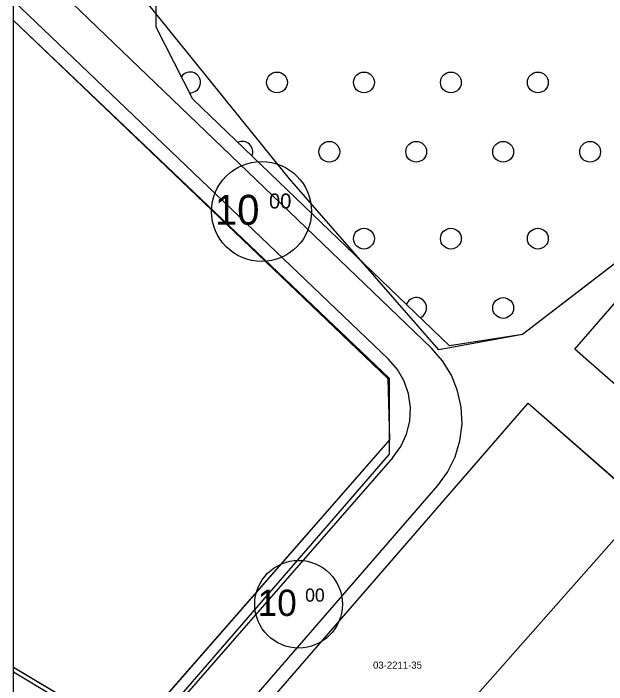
# Model space of a CAD drawing. Extents: x 413946 to 415528, y 4453939 to 4454944.
# Drawn here: x 413945.6 to 414028.6, y 4454334.2 to 4454428.2 of the extents above; entities that cross this region are included whole.
import ezdxf

# ---------------------------------------------------------------- set-up
doc = ezdxf.new("R2010")
doc.units = 0
for name, color, linetype in [('0_KADASTRO', 7, 'Continuous'), ('0_ÇERÇEVE', 7, 'Continuous'), ('Level 28', 7, 'Continuous'), ('Level 29', 7, 'Continuous'), ('Level 42', 7, 'Continuous'), ('Level 54', 7, 'Continuous'), ('Level 62', 7, 'Continuous'), ('SEMBOL', 7, 'Continuous')]:
    doc.layers.add(name, color=color, linetype=linetype)

msp = doc.modelspace()

# ---------------------------------------------------------------- linework, layer by layer
at = {"layer": '0_KADASTRO'}
for points in [[(414107.963, 4454432.627), (414089.276, 4454397.161), (414082.06, 4454401.15), (414059.63, 4454407.26), (414049.35, 4454408.22), (414042.038, 4454402.592), (414016.87, 4454383.22), (414005.15, 4454381.09), (413984.23, 4454405.06), (413963.56, 4454430.73)], [(413945.566, 4454335.9), (413945.566, 4454427.263)], [(413945.566, 4454427.263), (413998.2, 4454377.1), (413998.21, 4454366.46), (413962.78, 4454325.53), (413945.566, 4454335.9)]]:
    msp.add_lwpolyline(points, dxfattribs=at)
for points in [[(414024.21, 4454381.2), (414042.54, 4454402.37), (414065.08, 4454394.56), (414040.59, 4454366.81)], [(413971.79, 4454320.66), (414017.66, 4454373.64), (414033.97, 4454359.32), (413986.11, 4454305.11)], [(413986.11, 4454305.11), (414033.97, 4454359.32), (414065.92, 4454331.64), (414015.89, 4454273.36)]]:
    msp.add_lwpolyline(points, close=True, dxfattribs=at)
at = {"layer": '0_ÇERÇEVE'}
msp.add_lwpolyline([(413945.566, 4454943.957), (415494.137, 4454943.957), (415494.137, 4453939.478), (413945.566, 4453939.478)], close=True, dxfattribs=at)
at = {"layer": 'Level 28'}
for p, q in [((413945.566, 4454427.25), (413998.026, 4454377.098)), ((413970.715, 4454416.209), (413965.538, 4454426.303)), ((414006.623, 4454381.67), (413970.715, 4454416.209)), ((414049.35, 4454408.22), (414016.87, 4454383.22)), ((414016.87, 4454383.22), (414006.623, 4454381.67)), ((413998.026, 4454377.098), (413998.217, 4454368.455)), ((413971.79, 4454320.66), (414017.66, 4454373.64)), ((414017.66, 4454373.64), (414033.97, 4454359.32)), ((413998.217, 4454368.455), (413961.889, 4454326.835)), ((413961.889, 4454326.835), (413945.566, 4454336.587))]:
    msp.add_line(p, q, dxfattribs=at)
at = {"layer": 'Level 29'}
msp.add_line((413965.538, 4454426.303), (413965.538, 4454441.044), dxfattribs=at)
at = {"layer": 'Level 42'}
for centre in [(413982.483, 4454418.578), (413994.661, 4454418.578), (414006.839, 4454418.578), (414019.017, 4454418.578), (413989.801, 4454408.858), (414001.979, 4454408.858), (414014.157, 4454408.858), (414026.335, 4454408.858), (413994.661, 4454396.68), (414006.839, 4454396.68), (414019.017, 4454396.68), (414014.157, 4454386.96)]:
    msp.add_circle(centre, 1.458, dxfattribs=at)
for centre, start, end in [((413970.305, 4454418.578), 267.72643, 146.57823), ((413977.623, 4454408.858), 336.55024, 115.67635), ((414001.979, 4454386.96), 292.10672, 160.11986)]:
    msp.add_arc(centre, 1.458, start, end, dxfattribs=at)
at = {"layer": 'Level 54'}
for points in [[(413945.566, 4454336.587), (413945.566, 4454427.25)], [(413945.566, 4454427.25), (413998.026, 4454377.098), (413998.217, 4454368.455), (413961.889, 4454326.835), (413945.566, 4454336.587)]]:
    msp.add_lwpolyline(points, dxfattribs=at)
msp.add_lwpolyline([(414033.97, 4454359.32), (414065.92, 4454331.64), (414084.64, 4454316.14), (414032.68, 4454255.6), (414015.89, 4454273.36), (413986.11, 4454305.11), (413971.79, 4454320.66), (414017.66, 4454373.64)], close=True, dxfattribs=at)
at = {"layer": 'Level 62'}
for points in [[(414004.109, 4454381.314), (413947.91, 4454435.369)], [(413945.566, 4454430.016), (413998.098, 4454379.796)], [(414004.988, 4454362.06), (414006.377, 4454363.967), (414007.425, 4454366.08), (414008.104, 4454368.34), (414008.394, 4454370.681), (414008.286, 4454373.038), (414007.784, 4454375.343), (414006.902, 4454377.532), (414005.666, 4454379.541), (414004.109, 4454381.314)], [(413998.722, 4454365.992), (413999.831, 4454367.539), (414000.628, 4454369.268), (414001.082, 4454371.117), (414001.178, 4454373.019), (414000.911, 4454374.904), (414000.292, 4454376.704), (413999.343, 4454378.355), (413998.098, 4454379.796)], [(413998.722, 4454365.992), (413963.396, 4454325.52), (413953.573, 4454316.664)], [(413971.447, 4454323.319), (414004.988, 4454362.06)]]:
    msp.add_lwpolyline(points, dxfattribs=at)
at = {"layer": 'SEMBOL'}
for centre, radius in [((413980.319, 4454400.492), 7), ((413985.504, 4454345.436), 6.138)]:
    msp.add_circle(centre, radius, dxfattribs=at)

# ---------------------------------------------------------------- texts
at = {"layer": '0_KADASTRO'}
msp.add_text('03-2211-35', height=1, dxfattribs=at).set_placement((413995.935, 4454336.399))
at = {"layer": 'SEMBOL'}
for s, height, p in [('10', 4.2, (413973.779, 4454398.616)), ('00', 2.1, (413981.368, 4454400.899)), ('10', 3.6828, (413979.769, 4454343.791)), ('00', 1.8414, (413986.424, 4454345.793))]:
    msp.add_text(s, height=height, dxfattribs=at).set_placement(p)

doc.saveas('drawing.dxf')
